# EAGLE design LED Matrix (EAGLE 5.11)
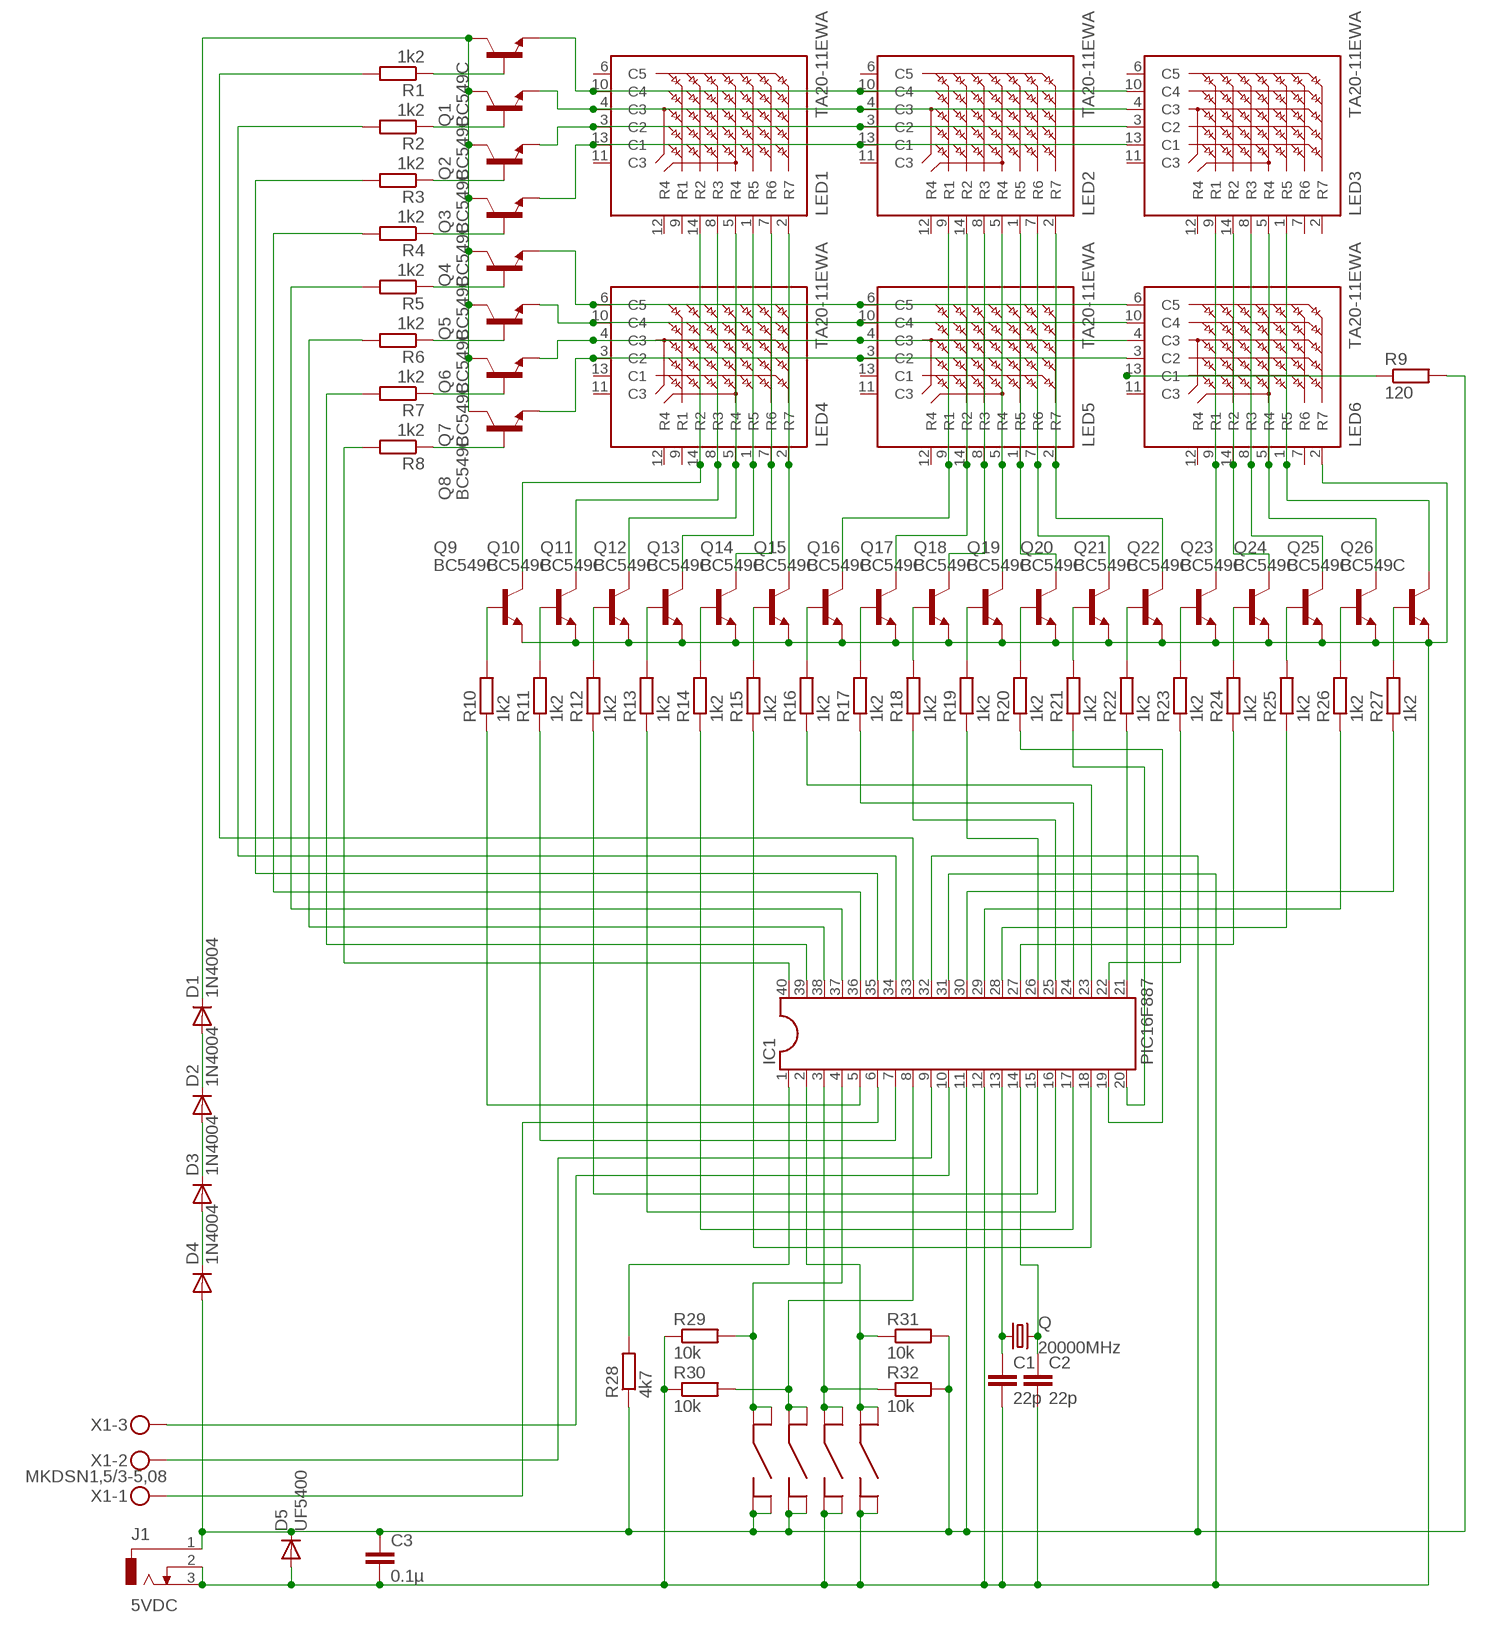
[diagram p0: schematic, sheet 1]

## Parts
C1  22p  C-EU025-025X050  [C025-025X050]
C2  22p  C-EU025-025X050  [C025-025X050]
C3  0.1µ  C-EU050-035X075  [C050-035X075]
D1  1N4004  [DO41-10]
D2  1N4004  [DO41-10]
D3  1N4004  [DO41-10]
D4  1N4004  [DO41-10]
D5  UF5400  [DO201-15]
IC1  PIC16F887  DIL40  [DIL40]
J1  5VDC  DCJ0303  [DCJ0303]
LED1  TA20-11EWA  [TA20-11HWA]
LED2  TA20-11EWA  [TA20-11HWA]
LED3  TA20-11EWA  [TA20-11HWA]
LED4  TA20-11EWA  [TA20-11HWA]
LED5  TA20-11EWA  [TA20-11HWA]
LED6  TA20-11EWA  [TA20-11HWA]
Q  20000MHz  CRYSTALHC49U-V  [HC49U-V]
Q1  BC549C  [TO92-EBC]
Q2  BC549C  [TO92-EBC]
Q3  BC549C  [TO92-EBC]
Q4  BC549C  [TO92-EBC]
Q5  BC549C  [TO92-EBC]
Q6  BC549C  [TO92-EBC]
Q7  BC549C  [TO92-EBC]
Q8  BC549C  [TO92-EBC]
Q9  BC549C  [TO92-EBC]
Q10  BC549C  [TO92-EBC]
Q11  BC549C  [TO92-EBC]
Q12  BC549C  [TO92-EBC]
Q13  BC549C  [TO92-EBC]
Q14  BC549C  [TO92-EBC]
Q15  BC549C  [TO92-EBC]
Q16  BC549C  [TO92-EBC]
Q17  BC549C  [TO92-EBC]
Q18  BC549C  [TO92-EBC]
Q19  BC549C  [TO92-EBC]
Q20  BC549C  [TO92-EBC]
Q21  BC549C  [TO92-EBC]
Q22  BC549C  [TO92-EBC]
Q23  BC549C  [TO92-EBC]
Q24  BC549C  [TO92-EBC]
Q25  BC549C  [TO92-EBC]
Q26  BC549C  [TO92-EBC]
R1  1k2  R-EU_0207/12  [0207/12]
R2  1k2  R-EU_0207/12  [0207/12]
R3  1k2  R-EU_0207/12  [0207/12]
R4  1k2  R-EU_0207/12  [0207/12]
R5  1k2  R-EU_0207/12  [0207/12]
R6  1k2  R-EU_0207/12  [0207/12]
R7  1k2  R-EU_0207/12  [0207/12]
R8  1k2  R-EU_0207/12  [0207/12]
R9  120  R-EU_0207/12  [0207/12]
R10  1k2  R-EU_0207/12  [0207/12]
R11  1k2  R-EU_0207/12  [0207/12]
R12  1k2  R-EU_0207/12  [0207/12]
R13  1k2  R-EU_0207/12  [0207/12]
R14  1k2  R-EU_0207/12  [0207/12]
R15  1k2  R-EU_0207/12  [0207/12]
R16  1k2  R-EU_0207/12  [0207/12]
R17  1k2  R-EU_0207/12  [0207/12]
R18  1k2  R-EU_0207/12  [0207/12]
R19  1k2  R-EU_0207/12  [0207/12]
R20  1k2  R-EU_0207/12  [0207/12]
R21  1k2  R-EU_0207/12  [0207/12]
R22  1k2  R-EU_0207/12  [0207/12]
R23  1k2  R-EU_0207/12  [0207/12]
R24  1k2  R-EU_0207/12  [0207/12]
R25  1k2  R-EU_0207/12  [0207/12]
R26  1k2  R-EU_0207/12  [0207/12]
R27  1k2  R-EU_0207/12  [0207/12]
R28  4k7  R-EU_0207/10  [0207/10]
R29  10k  R-EU_0207/10  [0207/10]
R30  10k  R-EU_0207/10  [0207/10]
R31  10k  R-EU_0207/10  [0207/10]
R32  10k  R-EU_0207/10  [0207/10]
S1  DRUKKNOP  [DRUKKNOP]
S2  DRUKKNOP  [DRUKKNOP]
S3  DRUKKNOP  [DRUKKNOP]
S4  DRUKKNOP  [DRUKKNOP]
X1  MKDSN1,5/3-5,08  [MKDSN1,5/3-5,08]

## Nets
5VDC: C3.1 D4.A D5.C IC1.11 IC1.32 J1.1 R9.2 R28.1 R31.2 R32.2 S1.P$2 S1.P$4 S2.P$2 S2.P$4
GND: C1.2 C2.2 C3.2 D5.A IC1.12 IC1.31 J1.2 J1.3 LED6.2(R7) Q9.E Q10.E Q11.E Q12.E Q13.E Q14.E Q15.E Q16.E Q17.E Q18.E Q19.E Q20.E Q21.E Q22.E Q23.E Q24.E Q25.E Q26.E R29.1 R30.1 S3.P$2 S3.P$4 S4.P$2 S4.P$4
N$1: IC1.5 R10.1
N$2: IC1.7 R11.1
N$3: IC1.16 R13.1
N$4: IC1.15 R12.1
N$5: IC1.17 R14.1
N$6: IC1.18 R15.1
N$7: IC1.23 R16.1
N$8: IC1.24 R17.1
N$9: LED2.5(R4) LED5.5(R4) Q18.C
N$10: LED2.8(R3) LED5.8(R3) Q17.C
N$11: LED2.1(R5) LED5.1(R5) Q19.C
N$12: LED2.14(R2) LED5.14(R2) Q16.C
N$13: LED2.9(R1) LED5.9(R1) Q15.C
N$14: LED2.7(R6) LED5.7(R6) Q20.C
N$15: LED2.2(R7) LED5.2(R7) Q21.C
N$16: LED3.9(R1) LED6.9(R1) Q22.C
N$17: LED3.14(R2) LED6.14(R2) Q23.C
N$18: LED3.8(R3) LED6.8(R3) Q24.C
N$19: LED3.5(R4) LED6.5(R4) Q25.C
N$20: LED3.1(R5) LED6.1(R5) Q26.C
N$21: LED1.2(R7) LED4.2(R7) Q14.C
N$22: LED1.7(R6) LED4.7(R6) Q13.C
N$23: LED1.1(R5) LED4.1(R5) Q12.C
N$24: LED1.5(R4) LED4.5(R4) Q11.C
N$25: LED1.8(R3) LED4.8(R3) Q10.C
N$26: LED1.14(R2) LED4.14(R2) Q9.C
N$27: IC1.25 R18.1
N$28: IC1.19 R20.1
N$29: IC1.20 R21.1
N$30: IC1.26 R19.1
N$31: IC1.21 R22.1
N$32: IC1.22 R23.1
N$33: IC1.27 R24.1
N$34: IC1.28 R25.1
N$35: IC1.29 R26.1
N$36: IC1.30 R27.1
N$37: Q9.B R10.2
N$38: Q17.B R18.2
N$39: Q10.B R11.2
N$40: Q11.B R12.2
N$41: Q12.B R13.2
N$42: Q13.B R14.2
N$43: Q14.B R15.2
N$44: Q15.B R16.2
N$45: Q16.B R17.2
N$46: Q18.B R19.2
N$47: Q19.B R20.2
N$48: Q20.B R21.2
N$49: Q21.B R22.2
N$50: Q22.B R23.2
N$51: Q23.B R24.2
N$52: Q24.B R25.2
N$53: Q25.B R26.2
N$54: Q26.B R27.2
N$55: IC1.1 R28.2
N$56: LED6.13(C1) R9.1
N$57: LED1.10(C4) LED2.10(C4) LED3.10(C4) Q1.E
N$58: LED1.4(C3) LED2.4(C3) LED3.4(C3) Q2.E
N$59: LED1.3(C2) LED2.3(C2) LED3.3(C2) Q3.E
N$60: LED1.13(C1) LED2.13(C1) LED3.13(C1) Q4.E
N$61: LED4.6(C5) LED5.6(C5) LED6.6(C5) Q5.E
N$62: LED4.3(C2) LED5.3(C2) LED6.3(C2) Q8.E
N$63: LED4.4(C3) LED5.4(C3) LED6.4(C3) Q7.E
N$64: LED4.10(C4) LED5.10(C4) LED6.10(C4) Q6.E
N$65: IC1.38 R6.2
N$66: IC1.37 R5.2
N$67: IC1.39 R7.2
N$68: IC1.40 R8.2
N$69: IC1.36 R4.2
N$70: IC1.35 R3.2
N$71: IC1.34 R2.2
N$72: IC1.33 R1.2
N$73: C1.1 IC1.13 Q.1
N$74: IC1.6 X1.1
N$75: C2.1 IC1.14 Q.2
N$76: D1.C Q1.C Q2.C Q3.C Q4.C Q5.C Q6.C Q7.C Q8.C
N$77: D3.A D4.C
N$78: IC1.3 R32.1 S3.P$1 S3.P$3
N$79: IC1.8 R30.2 S2.P$1 S2.P$3
N$80: IC1.4 R29.2 S1.P$1 S1.P$3
N$81: IC1.9 X1.2
N$82: IC1.10 X1.3
N$83: Q1.B R1.1
N$84: Q2.B R2.1
N$85: Q3.B R3.1
N$86: Q4.B R4.1
N$87: Q5.B R5.1
N$88: Q6.B R6.1
N$89: Q7.B R7.1
N$90: Q8.B R8.1
N$91: D1.A D2.C
N$92: D2.A D3.C
N$93: IC1.2 R31.1 S4.P$1 S4.P$3
Unconnected: LED1.6(C5) LED1.9(R1) LED1.11(C3) LED1.12(R4) LED2.6(C5) LED2.11(C3) LED2.12(R4) LED3.2(R7) LED3.6(C5) LED3.7(R6) LED3.11(C3) LED3.12(R4) LED4.9(R1) LED4.11(C3) LED4.12(R4) LED4.13(C1) LED5.11(C3) LED5.12(R4) LED5.13(C1) LED6.7(R6) LED6.11(C3) LED6.12(R4)

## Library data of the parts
C1-C3 = resistor:C-EU: CAPACITOR, European symbol
D1-D4 = diode:1N4004: DIODE
D5 = diode:UF5400: DIODE
IC1 = ic-package:DIL40: Dual In Line
J1 = con-jack:DCJ0303: DC POWER JACK Source: DCJ0303.pdf; OC_FARNELL: unknown; OC_NEWARK: unknown
LED1-LED6 = display-kingbright:TA20-11EWA: 50mm (2.0 INCH) 5x7 DOT MATRIX DISPLAY Source: http://www.kingbright.com/manager/upload/pdf/TC20-11EWA(Ver1189410378.9); OC_FARNELL: unknown; OC_NEWARK: unknown
Q = crystal:CRYSTAL: CRYSTAL; OC_FARNELL: 1666969; OC_NEWARK: unknown
Q1-Q26 = transistor-npn:BC549*: NPN Transistor
R1-R32 = resistor:R-EU_: RESISTOR, European symbol
S1-S4 = drukknop:DRUKKNOP: RAFI - 1.14.100.501/0000 - SOLDER TERMINAL, F/PCB, OUTWARD http://www.farnell.com/datasheets/10376.pdf
X1 = con-phoenix-508:MKDSN1,5/3-5,08: MKDSN 1,5/ 3-5,08 Printklemme Nennstrom: 13,5 A Nennspannung: 250 V Rastermaß: 5,08 mm Polzahl: 3 Anschlussart: Schraubanschluss Montage: Löten Anschlussrichtung Leiter/Platine: 0 ° Artikelnummer: 1729131 Source: http://eshop.phoenixcontact.com .. 1729131.pdf; MPN: SMKDSN1,5/3-5,08; OC_FARNELL: 1792904; OC_NEWARK: 70R0299

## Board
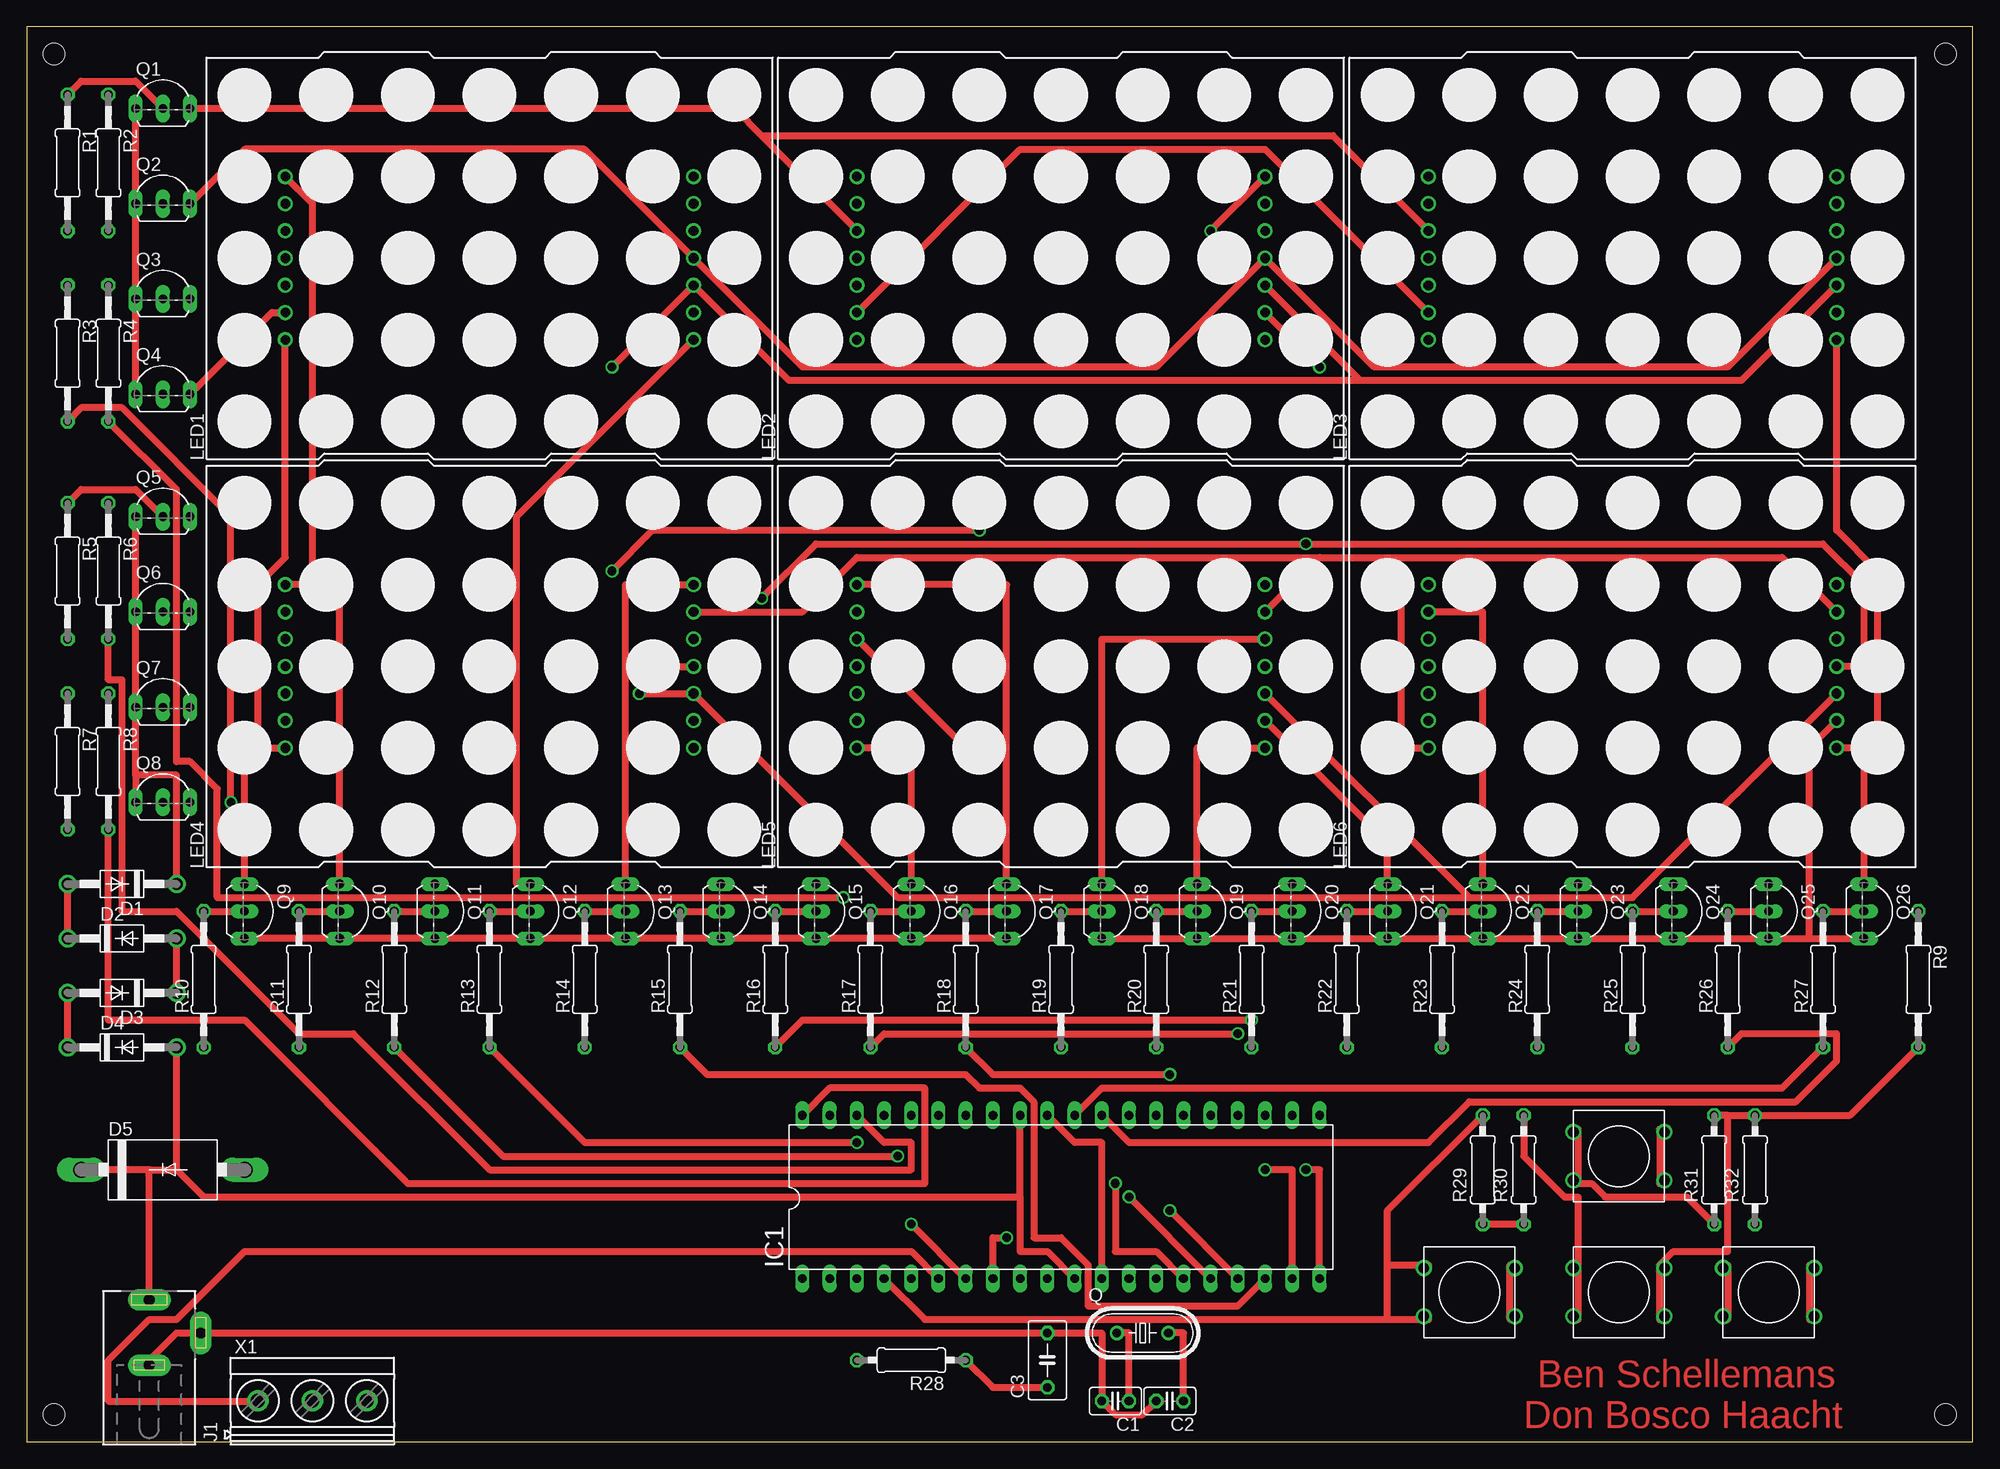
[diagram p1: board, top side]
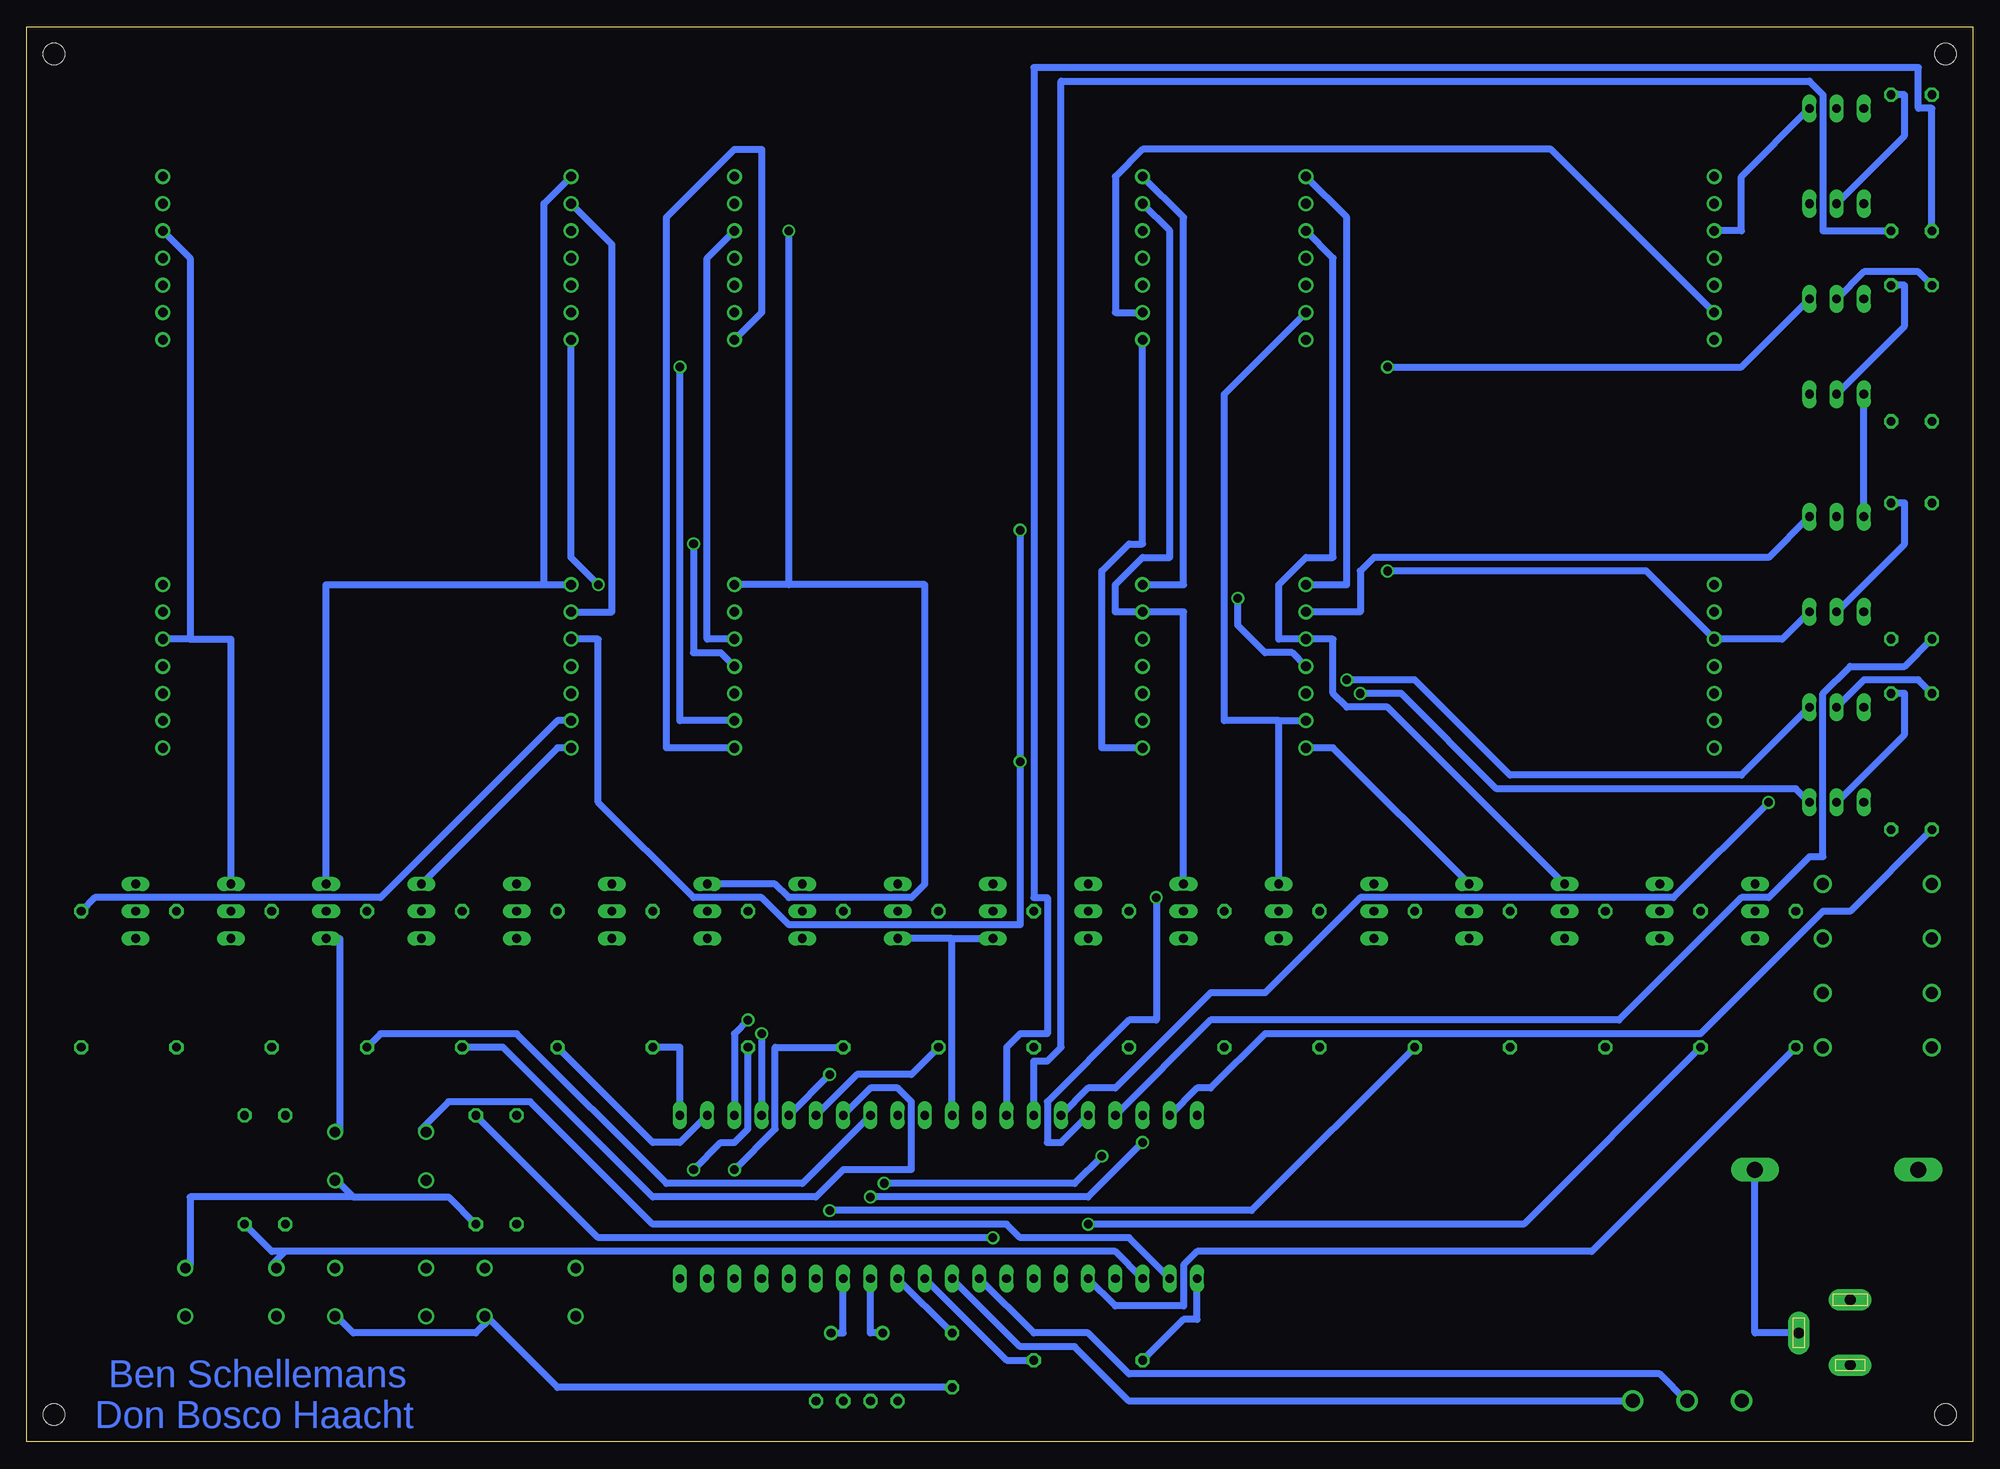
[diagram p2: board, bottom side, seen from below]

Size 181.61 x 132.08 mm. Coordinates in mm from the lower left corner, seen from the top.
Outline: 0,0 181.61,0 181.61,132.08 0,132.08 0,0
Copper layers (1*16): Top 0.035mm / dielectric 1.5mm / Bottom 0.035mm
Design rules "default *": minimum track width 0.65mm, minimum drill 0.8mm, track to track 0.25mm, track to pad 0.25mm, pad to pad 0.25mm, via to via 0.25mm, smd to smd 0.25mm, copper to edge 1mm, drill to drill 0.5mm, minimum pad ring 0.25mm, minimum via ring 0.2mm, stop-mask expansion 0.25mm, vias tented up to drill 0mil, thermal gap 0.25mm
Holes 2 mm at 2.54,2.54 2.54,129.54 179.07,2.54 179.07,129.54

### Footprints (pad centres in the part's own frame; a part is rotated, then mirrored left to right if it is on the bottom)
C025-025X050 = drill 0.813 octagon: 1 -1.27,0; 2 1.27,0
C050-035X075 = drill 0.813 octagon: 1 -2.54,0; 2 2.54,0
DO41-10 = drill 1.118 round: A 5.08,0; C -5.08,0
DO201-15 = drill 1.499 long: A 7.62,0; C -7.62,0
DIL40 = drill 0.813 long: 1 -24.13,-7.62; 2 -21.59,-7.62; 3 -19.05,-7.62; 4 -16.51,-7.62; 5 -13.97,-7.62; 6 -11.43,-7.62; 7 -8.89,-7.62; 8 -6.35,-7.62; 9 -3.81,-7.62; 10 -1.27,-7.62; 11 1.27,-7.62; 12 3.81,-7.62; 13 6.35,-7.62; 14 8.89,-7.62; 15 11.43,-7.62; 16 13.97,-7.62; 17 16.51,-7.62; 18 19.05,-7.62; 19 21.59,-7.62; 20 24.13,-7.62; 21 24.13,7.62; 22 21.59,7.62; 23 19.05,7.62; 24 16.51,7.62; 25 13.97,7.62; 26 11.43,7.62; 27 8.89,7.62; 28 6.35,7.62; 29 3.81,7.62; 30 1.27,7.62; 31 -1.27,7.62; 32 -3.81,7.62; 33 -6.35,7.62; 34 -8.89,7.62; 35 -11.43,7.62; 36 -13.97,7.62; 37 -16.51,7.62; 38 -19.05,7.62; 39 -21.59,7.62; 40 -24.13,7.62
DCJ0303 = drill 1 pad 2 long: 1 0,3.1; 2 4.8,0; 3 0,-3
TA20-11HWA = drill 0.9 pad 1.4 round: 1 -7.62,-19.05; 2 -5.08,-19.05; 3 -2.54,-19.05; 4 0,-19.05; 5 2.54,-19.05; 6 5.08,-19.05; 7 7.62,-19.05; 8 7.62,19.05; 9 5.08,19.05; 10 2.54,19.05; 11 0,19.05; 12 -2.54,19.05; 13 -5.08,19.05; 14 -7.62,19.05
HC49U-V = drill 0.813 round: 1 -2.413,0; 2 2.413,0
TO92-EBC = drill 0.813 long: B 0,-1.27; C -2.54,-1.27; E 2.54,-1.27
0207/12 = drill 0.813 octagon: 1 -6.35,0; 2 6.35,0
0207/10 = drill 0.813 octagon: 1 -5.08,0; 2 5.08,0
DRUKKNOP = drill 1 round: P$1 -4.25,2.25; P$2 4.25,2.25; P$3 -4.25,-2.25; P$4 4.25,-2.25
MKDSN1,5/3-5,08 = drill 1.3 pad 2 round: 1 -7.641,0.025; 2 -2.561,0.025; 3 2.519,0.025

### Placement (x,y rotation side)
C1  101.6,3.81 180 top
C2  106.68,3.81 180 top
C3  95.25,7.62 90 top
D1  8.89,52.07 180 top
D2  8.89,46.99 0 top
D3  8.89,41.91 180 top
D4  8.89,36.83 0 top
D5  12.7,25.4 0 top
IC1  96.52,22.86 0 top
J1  11.43,10.16 0 top
LED1  43.18,110.49 90 top
LED2  96.52,110.49 90 top
LED3  149.86,110.49 90 top
LED4  43.18,72.39 90 top
LED5  96.52,72.39 90 top
LED6  149.86,72.39 90 top
Q  104.14,10.16 0 top
Q1  12.7,125.73 0 top
Q2  12.7,116.84 0 top
Q3  12.7,107.95 0 top
Q4  12.7,99.06 0 top
Q5  12.7,87.63 0 top
Q6  12.7,78.74 0 top
Q7  12.7,69.85 0 top
Q8  12.7,60.96 0 top
Q9  21.59,49.53 270 top
Q10  30.48,49.53 270 top
Q11  39.37,49.53 270 top
Q12  48.26,49.53 270 top
Q13  57.15,49.53 270 top
Q14  66.04,49.53 270 top
Q15  74.93,49.53 270 top
Q16  83.82,49.53 270 top
Q17  92.71,49.53 270 top
Q18  101.6,49.53 270 top
Q19  110.49,49.53 270 top
Q20  119.38,49.53 270 top
Q21  128.27,49.53 270 top
Q22  137.16,49.53 270 top
Q23  146.05,49.53 270 top
Q24  154.94,49.53 270 top
Q25  163.83,49.53 270 top
Q26  172.72,49.53 270 top
R1  3.81,119.38 270 top
R2  7.62,119.38 270 top
R3  3.81,101.6 270 top
R4  7.62,101.6 270 top
R5  3.81,81.28 270 top
R6  7.62,81.28 270 top
R7  3.81,63.5 270 top
R8  7.62,63.5 270 top
R9  176.53,43.18 270 top
R10  16.51,43.18 90 top
R11  25.4,43.18 90 top
R12  34.29,43.18 90 top
R13  43.18,43.18 90 top
R14  52.07,43.18 90 top
R15  60.96,43.18 90 top
R16  69.85,43.18 90 top
R17  78.74,43.18 90 top
R18  87.63,43.18 90 top
R19  96.52,43.18 90 top
R20  105.41,43.18 90 top
R21  114.3,43.18 90 top
R22  123.19,43.18 90 top
R23  132.08,43.18 90 top
R24  140.97,43.18 90 top
R25  149.86,43.18 90 top
R26  158.75,43.18 90 top
R27  167.64,43.18 90 top
R28  82.55,7.62 180 top
R29  135.89,25.4 90 top
R30  139.7,25.4 90 top
R31  157.48,25.4 90 top
R32  161.29,25.4 90 top
S1  134.62,13.97 0 top
S2  148.59,13.97 0 top
S3  162.56,13.97 0 top
S4  148.59,26.67 0 top
X1  29.21,3.81 0 top

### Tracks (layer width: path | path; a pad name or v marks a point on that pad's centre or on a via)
5VDC
  Top 0.65: 13.97,25.4 D4.A | 11.43,25.4 D5.C | 11.43,25.4 13.97,25.4 | J1.1 11.43,25.4 | 158.75,30.48 R32.2 170.18,30.48 R9.2 | 158.75,30.48 R31.2 | S1.P$4 138.43,11.43 138.43,16.51 S1.P$2 | 152.4,16.51 152.4,11.43 S2.P$4 | R28.1 90.17,5.08 C3.1 | 92.71,22.86 92.71,17.78 95.25,17.78 IC1.11 | 92.71,22.86 IC1.32 | 158.75,30.48 158.75,17.78 153.67,17.78 152.4,16.51 | 152.4,16.51 S2.P$2 | 13.97,25.4 16.51,22.86 92.71,22.86
  Bottom 0.65: 138.43,11.43 139.7,10.16 151.13,10.16 152.4,11.43 S2.P$4 | IC1.11 90.17,7.62 R28.1 | 138.43,11.43 132.08,5.08 C3.1 | 138.43,11.43 S1.P$4
GND
  Top 0.65: S3.P$4 166.37,11.43 166.37,16.51 S3.P$2 | R30.1 R29.1 | S4.P$4 152.4,24.13 152.4,29.21 S4.P$2 | J1.3 11.43,7.62 13.97,10.16 J1.2 C3.2 100.33,10.16 C1.2 101.6,2.54 104.14,2.54 C2.2 | Q9.E Q10.E Q11.E Q12.E Q13.E Q14.E Q15.E Q16.E Q17.E | Q18.E Q19.E Q20.E Q21.E Q22.E Q23.E Q24.E Q25.E 166.37,46.99 | 166.37,46.99 Q26.E | LED6.2 166.37,64.77 166.37,46.99 | IC1.12 100.33,27.94 97.79,27.94 IC1.31
  Bottom 0.65: R30.1 142.24,22.86 151.13,22.86 | 151.13,22.86 152.4,24.13 S4.P$4 | 151.13,22.86 166.37,22.86 166.37,16.51 S3.P$2 | D5.A 20.32,10.16 J1.2 | C3.2 IC1.12 | IC1.31 95.25,46.99 | 95.25,46.99 Q17.E | 95.25,46.99 Q18.E | Q24.E 152.4,46.99 152.4,29.21 S4.P$2
N$1
  Bottom 0.65: R10.1 35.56,17.78 72.39,17.78 73.66,16.51 73.66,12.7 80.01,12.7 IC1.5
N$2  (via drill 0.8)
  Top 0.65: v82.55,20.32 IC1.7
  Bottom 0.65: R11.1 41.91,20.32 v82.55,20.32
N$3  (via drill 0.8)
  Top 0.65: R13.1 52.07,27.94 v77.47,27.94 | v102.87,22.86 IC1.16
  Bottom 0.65: v77.47,27.94 82.55,22.86 v102.87,22.86
N$4  (via drill 0.8)
  Top 0.65: R12.1 44.45,26.67 v81.28,26.67 | v101.6,24.13 101.6,17.78 105.41,17.78 IC1.15
  Bottom 0.65: v81.28,26.67 83.82,24.13 v101.6,24.13
N$5  (via drill 0.8)
  Top 0.65: v106.68,21.59 IC1.17
  Bottom 0.65: R14.1 67.31,21.59 v106.68,21.59
N$6
  Top 0.65: R15.1 63.5,34.29 87.63,34.29 88.9,33.02 92.71,33.02 93.98,31.75 93.98,19.05 96.52,19.05 99.06,16.51 99.06,12.7 113.03,12.7 IC1.18
N$7  (via drill 0.8)
  Top 0.65: R16.1 72.39,39.37 v114.3,39.37
  Bottom 0.65: v114.3,39.37 115.57,38.1 IC1.23
N$8  (via drill 0.8)
  Top 0.65: R17.1 80.01,38.1 v113.03,38.1
  Bottom 0.65: v113.03,38.1 IC1.24
N$9
  Top 0.65: Q18.C 100.33,74.93 LED5.5
  Bottom 0.65: LED2.5 118.11,110.49 118.11,74.93 LED5.5
N$10
  Top 0.65: Q17.C 91.44,80.01 LED5.8
  Bottom 0.65: LED2.8 73.66,114.3 73.66,80.01 LED5.8
N$11
  Top 0.65: Q19.C 109.22,64.77 LED5.1
  Bottom 0.65: LED2.1 113.03,105.41 113.03,120.65 115.57,120.65 121.92,114.3 121.92,64.77 LED5.1
N$12
  Top 0.65: Q16.C 82.55,64.77 LED5.14
  Bottom 0.65: LED2.14 77.47,83.82 78.74,83.82 81.28,81.28 81.28,64.77 LED5.14
N$13
  Bottom 0.65: Q15.C 73.66,77.47 LED5.9 80.01,77.47 80.01,80.01 77.47,82.55 74.93,82.55 74.93,113.03 LED2.9
N$14  (via drill 0.8)
  Top 0.65: v110.49,113.03 LED2.7
  Bottom 0.65: Q20.C 111.76,52.07 110.49,50.8 99.06,50.8 97.79,52.07 97.79,80.01 110.49,80.01 | 110.49,80.01 LED5.7 | 110.49,80.01 v110.49,113.03
N$15  (via drill 0.8)
  Top 0.65: Q21.C 127,55.88 LED5.2 | v120.65,100.33 LED2.2
  Bottom 0.65: v120.65,100.33 120.65,67.31 LED5.2
N$16
  Top 0.65: Q22.C 135.89,77.47 LED6.9
  Bottom 0.65: LED3.9 127,111.76 127,77.47 LED6.9
N$17  (via drill 0.8)
  Top 0.65: v128.27,80.01 128.27,64.77 LED6.14
  Bottom 0.65: Q23.C 132.08,64.77 LED6.14 | LED3.14 130.81,82.55 v128.27,80.01
N$18
  Bottom 0.65: Q24.C 153.67,80.01 133.35,80.01 | 133.35,80.01 LED6.8 | LED3.8 133.35,115.57 133.35,80.01
N$19
  Bottom 0.65: Q25.C 162.56,74.93 166.37,74.93 | 166.37,74.93 LED6.5 | LED3.5 166.37,110.49 166.37,74.93
N$20
  Top 0.65: 171.45,64.77 Q26.C | 171.45,64.77 LED6.1 | LED3.1 168.91,85.09 172.72,81.28 172.72,64.77 171.45,64.77
N$21
  Bottom 0.65: Q14.C 64.77,67.31 | 64.77,67.31 LED4.2 | LED1.2 69.85,97.79 69.85,67.31 64.77,67.31
N$22
  Top 0.65: Q13.C 55.88,80.01 LED4.7
  Bottom 0.65: LED1.7 58.42,114.3 58.42,80.01 LED4.7
N$23
  Top 0.65: LED1.1 45.72,86.36 45.72,52.07 Q12.C
  Bottom 0.65: Q12.C 59.69,64.77 LED4.1
N$24
  Bottom 0.65: Q11.C 54.61,68.58 58.42,68.58 59.69,69.85 59.69,74.93 LED4.5 64.77,74.93 64.77,80.01 62.23,82.55 59.69,82.55 59.69,110.49 LED1.5
N$25
  Top 0.65: Q10.C 29.21,80.01 26.67,80.01 | 26.67,80.01 LED4.8 | LED1.8 26.67,115.57 26.67,80.01
N$26
  Top 0.65: Q9.C 20.32,64.77 21.59,64.77 | 21.59,64.77 LED4.14 | LED1.14 24.13,82.55 21.59,80.01 21.59,64.77
N$27  (via drill 0.8)
  Top 0.65: R18.1 90.17,34.29 v106.68,34.29
  Bottom 0.65: v106.68,34.29 IC1.25
N$28  (via drill 0.8)
  Top 0.65: IC1.19 118.11,25.4 v115.57,25.4
  Bottom 0.65: v115.57,25.4 111.76,29.21 111.76,36.83 R20.1
N$29  (via drill 0.8)
  Top 0.65: IC1.20 120.65,25.4 v119.38,25.4
  Bottom 0.65: v119.38,25.4 116.84,27.94 115.57,27.94 114.3,29.21 R21.1
N$30
  Bottom 0.65: R19.1 99.06,34.29 104.14,34.29 IC1.26
N$31
  Bottom 0.65: IC1.21 120.65,36.83 R22.1
N$32
  Bottom 0.65: IC1.22 120.65,27.94 123.19,27.94 R23.1
N$33
  Bottom 0.65: IC1.27 102.87,33.02 100.33,33.02 99.06,31.75 99.06,25.4 105.41,25.4 107.95,22.86 123.19,22.86 137.16,36.83 R24.1
N$34
  Bottom 0.65: IC1.28 109.22,24.13 121.92,24.13 135.89,38.1 148.59,38.1 R25.1
N$35
  Top 0.65: IC1.29 102.87,27.94 130.81,27.94 134.62,31.75 165.1,31.75 168.91,35.56 168.91,38.1 160.02,38.1 R26.1
N$36
  Top 0.65: IC1.30 100.33,33.02 163.83,33.02 R27.1
N$37
  Top 0.65: R10.2 Q9.B
N$38
  Top 0.65: R18.2 Q17.B
N$39
  Top 0.65: R11.2 Q10.B
N$40
  Top 0.65: R12.2 Q11.B
N$41
  Top 0.65: R13.2 Q12.B
N$42
  Top 0.65: R14.2 Q13.B
N$43
  Top 0.65: R15.2 Q14.B
N$44
  Top 0.65: R16.2 Q15.B
N$45
  Top 0.65: R17.2 Q16.B
N$46
  Top 0.65: R19.2 Q18.B
N$47
  Top 0.65: R20.2 Q19.B
N$48
  Top 0.65: R21.2 Q20.B
N$49
  Top 0.65: R22.2 Q21.B
N$50
  Top 0.65: R23.2 Q22.B
N$51
  Top 0.65: R24.2 Q23.B
N$52
  Top 0.65: R25.2 Q24.B
N$53
  Top 0.65: R26.2 Q25.B
N$54
  Top 0.65: R27.2 Q26.B
N$55
  Bottom 0.65: R28.2 73.66,11.43 72.39,11.43 IC1.1
N$56
  Bottom 0.65: R9.1 175.26,50.8 148.59,50.8 132.08,67.31 LED6.13
N$57
  Top 0.65: 68.58,121.92 66.04,124.46 Q1.E | 68.58,121.92 LED2.10 | LED3.10 121.92,121.92 68.58,121.92
  Bottom 0.65: Q1.E 21.59,118.11 21.59,113.03 LED1.10
N$58
  Top 0.65: Q2.E 20.32,120.65 52.07,120.65 LED1.4 72.39,100.33 105.41,100.33 LED2.4 125.73,100.33 158.75,100.33 LED3.4
N$59  (via drill 0.8)
  Top 0.65: v54.61,100.33 LED1.3 71.12,99.06 124.46,99.06 | 124.46,99.06 LED2.3 | 124.46,99.06 160.02,99.06 LED3.3
  Bottom 0.65: Q3.E 21.59,100.33 v54.61,100.33
N$60
  Top 0.65: Q4.E 22.86,105.41 LED1.13 | LED2.13 92.71,120.65 115.57,120.65 LED3.13
  Bottom 0.65: LED1.13 39.37,120.65 77.47,120.65 80.01,118.11 80.01,105.41 LED2.13
N$61
  Top 0.65: 120.65,82.55 LED5.6 | 120.65,82.55 163.83,82.55 LED6.6 | LED4.6 72.39,77.47 77.47,82.55 120.65,82.55
  Bottom 0.65: Q5.E 19.05,82.55 55.88,82.55 57.15,81.28 57.15,77.47 LED4.6
N$62  (via drill 0.8)
  Top 0.65: v57.15,69.85 LED4.3 81.28,50.8 134.62,50.8 | 134.62,50.8 LED5.3 | 134.62,50.8 149.86,50.8 LED6.3
  Bottom 0.65: Q8.E 16.51,60.96 44.45,60.96 53.34,69.85 v57.15,69.85
N$63  (via drill 0.8)
  Top 0.65: v58.42,71.12 59.69,72.39 LED4.4 | LED6.4 171.45,72.39 171.45,80.01 167.64,83.82 v119.38,83.82 73.66,83.82 v68.58,78.74
  Bottom 0.65: Q7.E 21.59,62.23 43.18,62.23 52.07,71.12 v58.42,71.12 | LED5.4 116.84,73.66 119.38,73.66 v119.38,83.82 | LED4.4 63.5,73.66 66.04,73.66 68.58,76.2 v68.58,78.74
N$64  (via drill 0.8)
  Top 0.65: v88.9,63.5 LED5.10 | v54.61,81.28 58.42,85.09 v88.9,85.09
  Bottom 0.65: Q6.E 17.78,74.93 LED4.10 30.48,81.28 v54.61,81.28 | LED6.10 128.27,74.93 128.27,59.69 119.38,50.8 113.03,50.8 110.49,48.26 88.9,48.26 v88.9,63.5 v88.9,85.09
N$65
  Top 0.65: R6.2 7.62,71.12 8.89,71.12 8.89,49.53 13.97,49.53 25.4,38.1 30.48,38.1 43.18,25.4 82.55,25.4 82.55,27.94 80.01,27.94 IC1.38
N$66
  Bottom 0.65: R5.2 6.35,72.39 11.43,72.39 13.97,69.85 13.97,54.61 15.24,54.61 19.05,50.8 21.59,50.8 33.02,39.37 71.12,39.37 IC1.37
N$67
  Bottom 0.65: R7.2 11.43,49.53 13.97,49.53 25.4,38.1 66.04,38.1 71.12,33.02 72.39,33.02 IC1.39
N$68
  Top 0.65: R8.2 7.62,39.37 20.32,39.37 35.56,24.13 83.82,24.13 83.82,33.02 74.93,33.02 IC1.40
N$69  (via drill 0.8)
  Top 0.65: R4.2 13.97,88.9 13.97,63.5 15.24,63.5 17.78,60.96 17.78,50.8 v76.2,50.8
  Bottom 0.65: v76.2,50.8 76.2,39.37 78.74,39.37 86.36,31.75 86.36,27.94 85.09,27.94 IC1.36
N$70  (via drill 0.8)
  Top 0.65: R3.2 5.08,96.52 8.89,96.52 19.05,86.36 v19.05,59.69
  Bottom 0.65: v19.05,59.69 27.94,50.8 57.15,50.8 66.04,41.91 71.12,41.91 80.01,33.02 82.55,33.02 IC1.35
N$71
  Bottom 0.65: IC1.34 87.63,35.56 86.36,35.56 85.09,36.83 85.09,127 15.24,127 13.97,125.73 13.97,113.03 R2.2
N$72
  Bottom 0.65: R1.2 3.81,124.46 5.08,124.46 5.08,128.27 87.63,128.27 87.63,50.8 86.36,50.8 86.36,38.1 88.9,38.1 90.17,36.83 IC1.33
N$73
  Top 0.65: C1.1 102.87,10.16 Q.1 101.6,10.16
  Bottom 0.65: IC1.13 102.87,10.16 Q.1 101.6,10.16
N$74
  Top 0.65: IC1.6 82.55,17.78 20.32,17.78 13.97,11.43 11.43,11.43 7.62,7.62 7.62,3.81 21.59,3.81 X1.1
N$75
  Top 0.65: C2.1 107.95,10.16 Q.2
  Bottom 0.65: IC1.14 105.41,10.16 Q.2 106.68,10.16
N$76
  Top 0.65: Q4.C Q3.C Q2.C Q1.C | Q5.C Q6.C Q7.C 10.16,62.23 | 10.16,62.23 Q8.C | D1.C 13.97,62.23 10.16,62.23
  Bottom 0.65: Q5.C Q4.C
N$77
  Top 0.65: D4.C D3.A
N$78
  Top 0.65: S3.P$3 158.75,11.43 158.75,16.51 S3.P$1
  Bottom 0.65: IC1.3 80.01,17.78 157.48,17.78 | 157.48,17.78 158.75,16.51 S3.P$1 | R32.1 158.75,17.78 157.48,17.78
N$79  (via drill 0.8)
  Top 0.65: 144.78,16.51 144.78,11.43 S2.P$3 | IC1.8 90.17,19.05 v91.44,19.05 | 144.78,16.51 144.78,22.86 143.51,22.86 139.7,26.67 R30.2 | 144.78,16.51 S2.P$1
  Bottom 0.65: v91.44,19.05 128.27,19.05 R30.2
N$80
  Top 0.65: IC1.4 83.82,11.43 127,11.43 | 127,11.43 130.81,11.43 S1.P$3 | R29.2 127,21.59 127,16.51 | 127,11.43 127,16.51 | 127,16.51 130.81,16.51 S1.P$1
N$81
  Bottom 0.65: IC1.9 87.63,10.16 82.55,10.16 78.74,6.35 29.21,6.35 26.67,3.81 X1.2
N$82
  Bottom 0.65: IC1.10 88.9,8.89 83.82,8.89 78.74,3.81 31.75,3.81 X1.3
N$83
  Top 0.65: R1.1 5.08,127 10.16,127 Q1.B
N$84
  Bottom 0.65: Q2.B 6.35,121.92 6.35,125.73 R2.1
N$85
  Bottom 0.65: R3.1 5.08,109.22 10.16,109.22 Q3.B
N$86
  Bottom 0.65: Q4.B 6.35,104.14 6.35,107.95 R4.1
N$87
  Top 0.65: R5.1 5.08,88.9 10.16,88.9 Q5.B
N$88
  Bottom 0.65: Q6.B 6.35,83.82 6.35,87.63 R6.1
N$89
  Bottom 0.65: R7.1 5.08,71.12 10.16,71.12 Q7.B
N$90
  Bottom 0.65: Q8.B 6.35,66.04 6.35,69.85 R8.1
N$91
  Top 0.65: D2.C D1.A
N$92
  Top 0.65: D3.C D2.A
N$93
  Top 0.65: R31.1 154.94,22.86 147.32,22.86 146.05,24.13 144.78,24.13 | 144.78,24.13 144.78,29.21 S4.P$1 | 144.78,24.13 S4.P$3
  Bottom 0.65: IC1.2 78.74,19.05 88.9,19.05 90.17,20.32 123.19,20.32 134.62,31.75 142.24,31.75 144.78,29.21 S4.P$1

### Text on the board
Top: Ben Schellemans | Don Bosco Haacht
Bottom: Ben Schellemans | Don Bosco Haacht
